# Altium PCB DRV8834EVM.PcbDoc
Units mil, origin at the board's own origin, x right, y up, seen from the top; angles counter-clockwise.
Board outline 5000 x 4500 mil, 2 copper layers (Top Layer, Bottom Layer); 84 components, 82 nets, 320 pads, 109 vias.
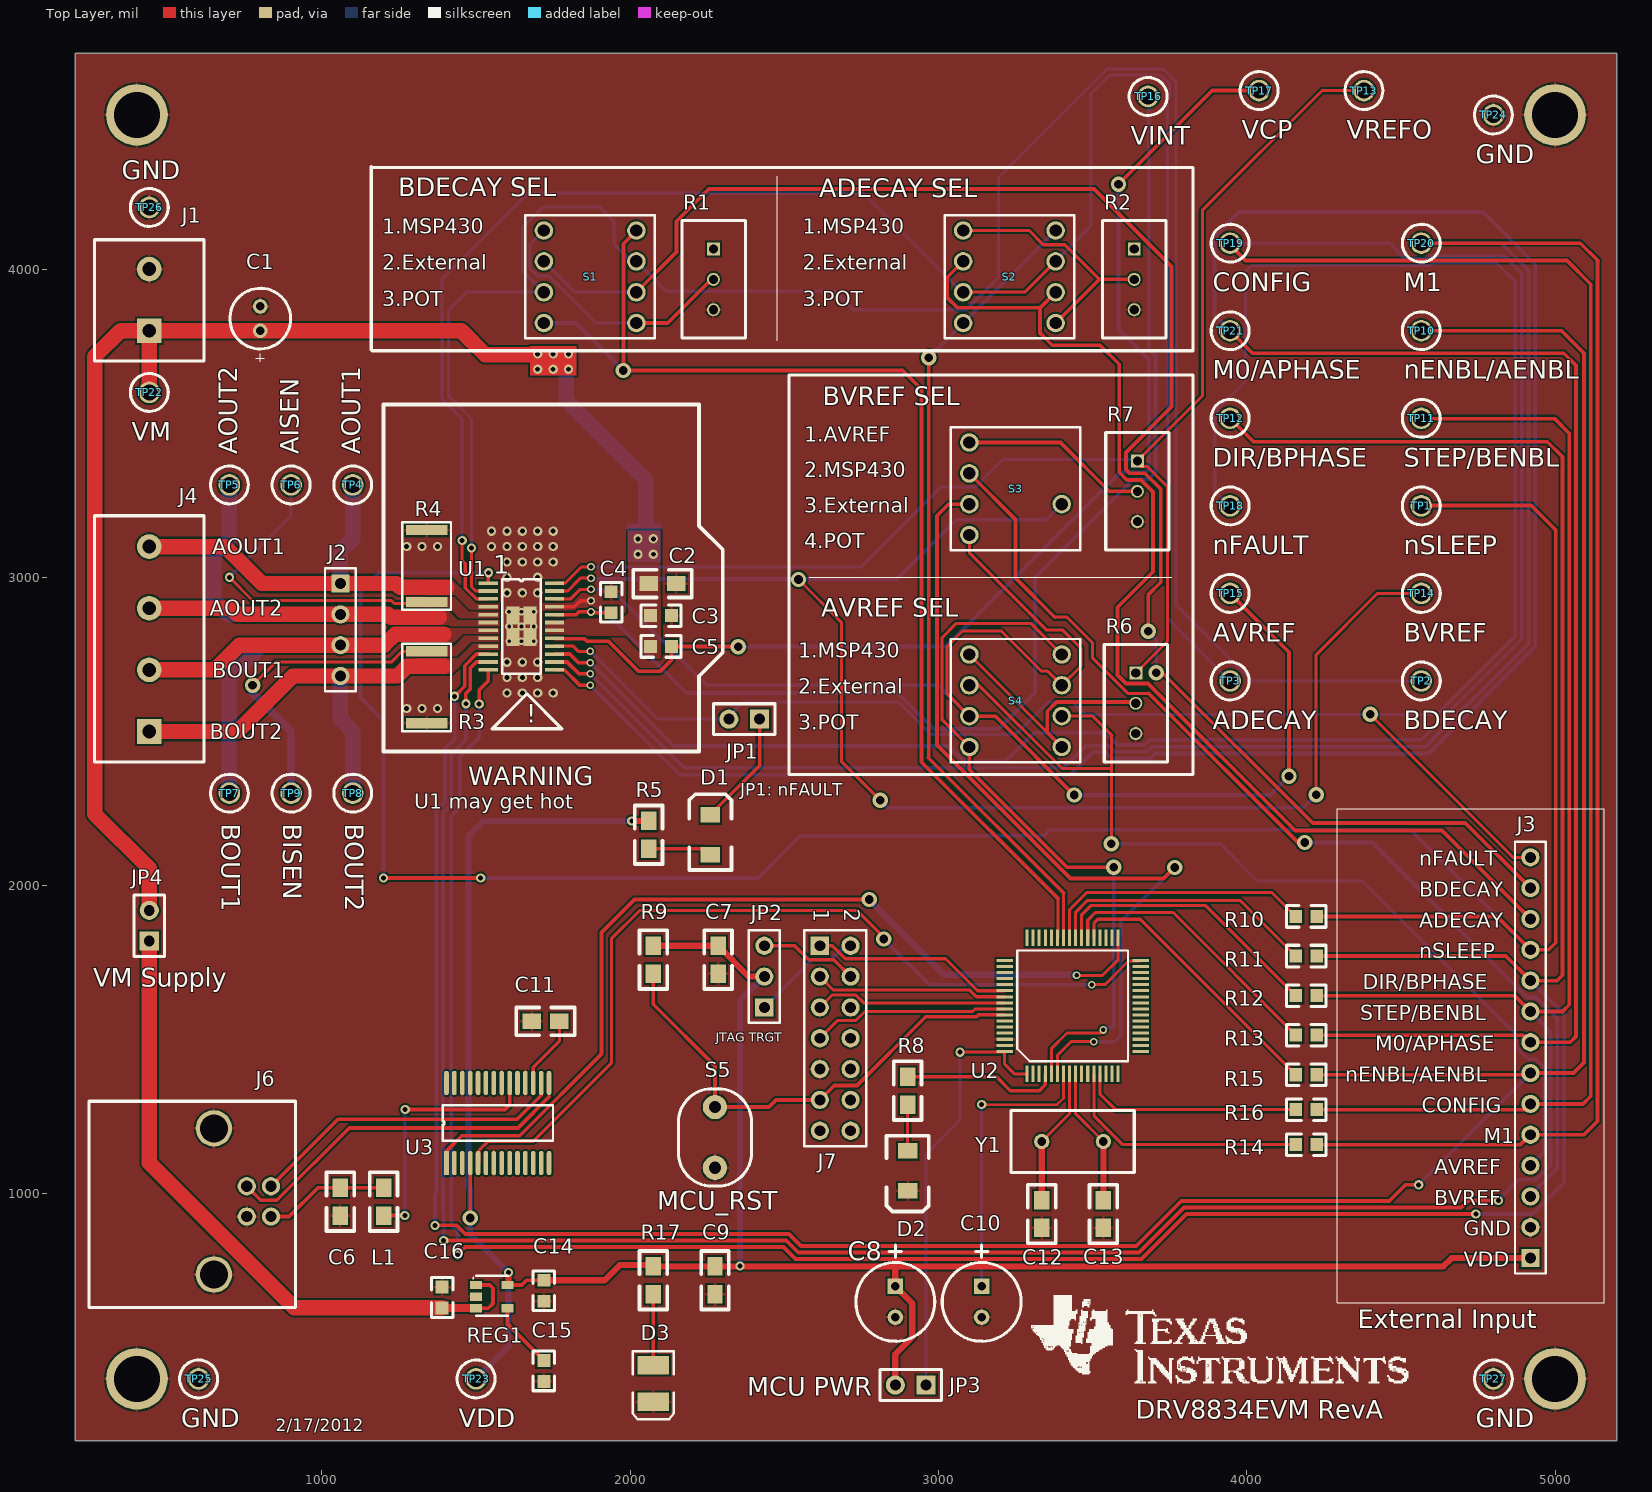
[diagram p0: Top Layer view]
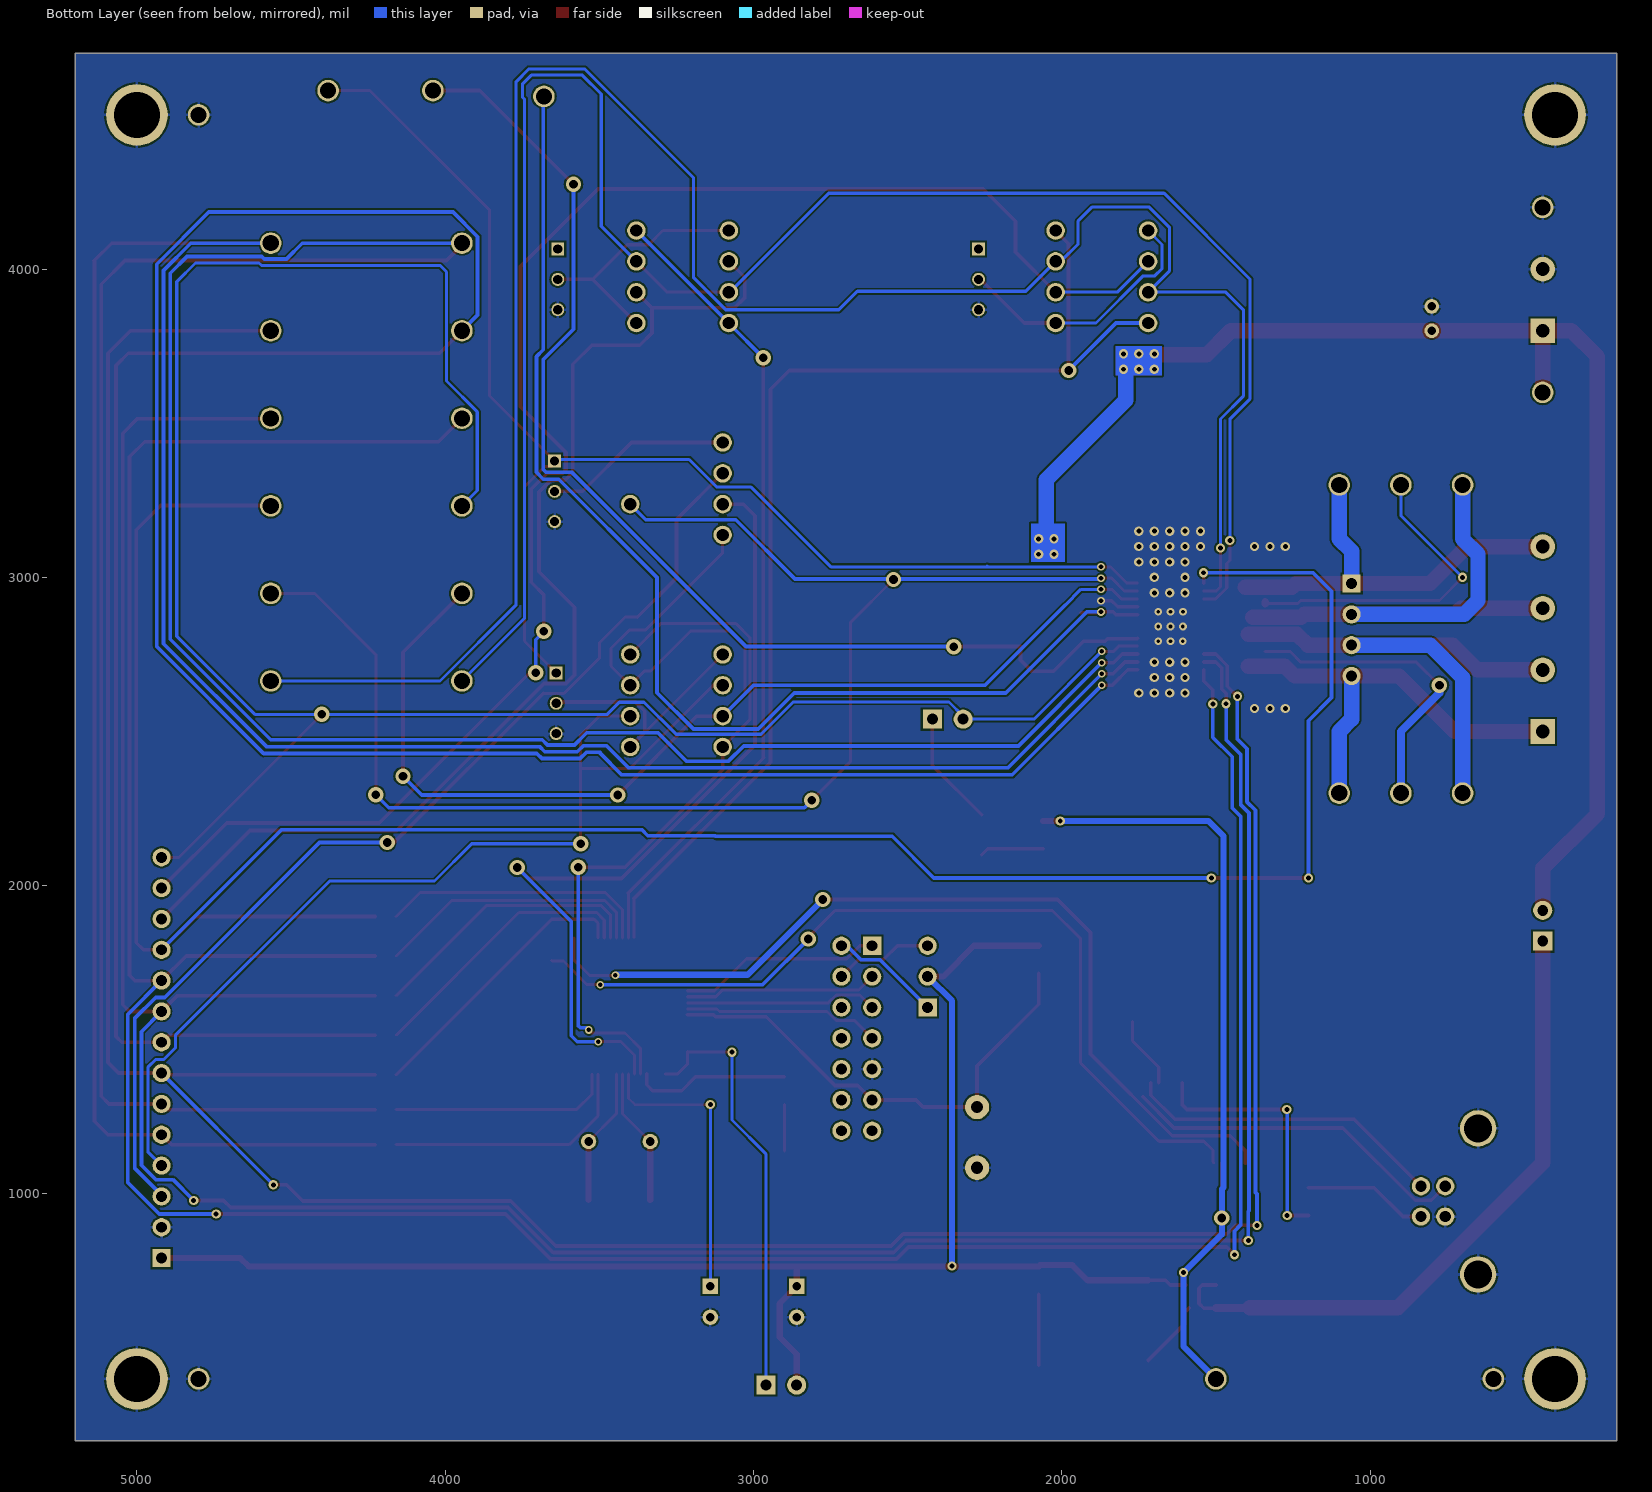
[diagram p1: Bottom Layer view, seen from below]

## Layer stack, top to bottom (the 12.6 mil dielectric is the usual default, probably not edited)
Top Layer: signal copper 1.4
Dielectric: dielectric 12.6, FR-4, Dk 4.8
Bottom Layer: signal copper 1.4

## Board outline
200,200 5200,200 5200,4700 200,4700 200,200

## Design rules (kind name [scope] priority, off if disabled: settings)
Clearance [All] p1: gap=6
HoleSize [All] p1: absolutevalues=TRUE maxlimit=150 minlimit=1 maxpercent=80.000 minpercent=20.000
HoleToHoleClearance [All] p1: gap=5 allowstackedmicrovias=TRUE
MinimumSolderMaskSliver [All] p1: minsoldermaskwidth=2
PasteMaskExpansion [All] p1: expansion=5
PolygonConnect PolygonConnect_2 [All vs IsNamedPolygon('TOP_BOUT2') Or  IsNamedPolygon('TOP_BOUT1') Or  IsNamedPolygon('TOP_BISEN') Or  IsNamedPolygon('TOP_AOUT2') Or  IsNamedPolygon('TOP_AISEN') Or  IsNamedPolygon('TOP_VM') Or  IsNamedPolygon('TOP_AOUT1')] p1: connectstyle=Direct reliefconductorwidth=10 reliefentries=4 polygonreliefangle="90 Angle"
PolygonConnect PolygonConnect_1 [All vs (InComponent('U1') or IsVia) AND InNet('GND')] p2: connectstyle=Direct reliefconductorwidth=10 reliefentries=4 polygonreliefangle="90 Angle"
PolygonConnect [All] p3: connectstyle=Relief reliefconductorwidth=10 reliefentries=4 polygonreliefangle="90 Angle"
RoutingVias [All] p1: holewidth=28 width=50 viastyle="Through Hole" minholewidth=10 minwidth=15 maxholewidth=150 maxwidth=150
SilkToSilkClearance [All] p1: silktosilkclearance=5
SilkscreenOverComponentPads [All] p1: minsilkscreentomaskgap=3
SolderMaskExpansion [All] p1: expansion=3
TestPointUsage [All] p1: valid=0 allowmultiple=FALSE
Testpoint [All] p1: side=15 testpointundercomponent=TRUE minsize=40 maxsize=100 preferedsize=60 minholesize=0 maxholesize=40 preferedholesize=32 testpointgrid=1 style=1023 order=0-112345678
Width [All] p1: maxlimit=100 minlimit=8 preferedwidth=10
18 further rules are at their usual default settings.

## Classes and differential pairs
component class DRV8834EVM_MSP430: C6 C7 C8 C9 C10 C11 C12 C13 C14 C15 C16 D2 D3 J6 J7 JP2 JP3 JP4 L1 R8 R9 R10 R11 R12 R13 R14 R15 R16 R17 REG1 S5 U2 U3 Y1
component class DRV8834EVM: AVREF BVREF C1 C2 C3 C4 C5 D1 GND J1 J2 J3 J4 JP1 R1 R2 R3 R4 R5 R6 R7 S1 S2 S3 S4 TP1 TP2 TP3 TP4 TP5 TP6 TP7 TP8 TP9 TP10 TP11 TP12 TP13 TP14 TP15 TP16 TP17 TP18 TP19 TP20 TP21 TP22 TP23 TP24 TP25 TP26 TP27 U1

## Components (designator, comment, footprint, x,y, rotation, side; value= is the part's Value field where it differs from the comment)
C1 "" "RB 2.0mm/5mm_NoPost" 800,3878.74 r270 top
C2 "" 0805 2150,2980 r180 top
C3 "" 0603 2134,2876 r180 top
C4 "" 0603 1938,2953.11 r270 top
C5 "" 0603 2065.89,2776 r0 top
C6 "" 0805 1060,930 r90 top
C7 "" 0805 2285,1715 r90 top
C8 "Cap Pol1" "RB .1/.250" 2860,600 r270 top
C9 "" 0805 2275,675 r90 top
C10 "Cap Pol1" "RB .1/.250" 3140,600 r270 top
C11 "" 0805 1680,1560 r0 top
C12 "Cap" 0805 3335,890 r90 top
C13 "Cap" 0805 3535,890 r90 top
C14 "2.2uF" 0603 1720,720 r270 top
C15 ".01uF" 0603 1720,460 r270 top
C16 "" 0603 1390,697.81 r270 top
D1 "nFAULT" 1206_LED 2260,2100 r90 top
D2 "Status" 1206_LED 2900,1140 r270 top
D3 "3.3V" 3.5X2.8X1.9 2075,385 r270 top
J1 "PWR" PWR_CONN2 440,3800 r90 top
J2 "Header 4" HDR1X4 1060,2980 r270 top
J3 "Input" HDR1X14 4920,792 r90 top
J4 "OUT" PWR_CONN4 440,2500 r90 top
J6 "USB B Conn" USB_CONN 756.26,1025 r270 top
J7 "JTAG" MSP430_JTAG 2615,1805 r270 top
JP1 "nFAULT" JMP0.2 2420,2540 r180 top
JP2 "PWR Select" HDR1X3 2435,1605 r90 top
JP3 "MCU PWR" JMP0.2 2960,380 r180 top
JP4 "VM" JMP0.2 440,1820 r90 top
L1 "" 0805 1200,1020 r270 top
R1 "" "PV36 Pot" 2270,4065.04 r0 top
R2 "" "PV36 Pot" 3635,4065.04 r0 top
R3 "" 2512 1340,2526.54 r90 top locked
R4 "" 2512 1340,3153.46 r270 top locked
R5 "" 0805 2060,2210 r270 top
R6 "" "PV36 Pot" 3640,2690.04 r0 top
R7 "" "PV36 Pot" 3645,3377.54 r0 top
R8 "Res2" 0805 2900,1290 r90 top
R9 "Res2" 0805 2075,1715 r90 top
R10 "Res1" 0603 4159.09,1900 r0 top
R11 "Res1" 0603 4159.09,1771.67 r0 top
R12 "Res1" 0603 4159.09,1643.33 r0 top
R13 "Res1" 0603 4159.09,1515 r0 top
R14 "Res1" 0603 4227,1160 r180 top
R15 "Res1" 0603 4159.09,1386.67 r0 top
R16 "Res1" 0603 4227,1273.33 r180 top
R17 "" 0805 2075,675 r90 top
REG1 "Volt_Reg LP2985" LP2985 1500,704.51 r270 top
S1 "BDECAY SEL" "SS10 3 Pos Selector - duplicate" 1720,4125 r0 top
S2 "ADECAY SEL" "SS10 3 Pos Selector - duplicate" 3080,4125 r0 top
S3 "BVREF SEL" "SS10 4 POS SELECTOR" 3100,3437.5 r0 top
S4 "AVREF SEL" "SS10 3 Pos Selector - duplicate" 3100,2750 r0 top
S5 "MCU-RST" Pana_PB 2275,1085 r90 top
TP1 "nSLEEP" "TEST POINT 0.052" 4566,3232 r0 top
TP2 "BDECAY" "TEST POINT 0.052" 4566,2664 r0 top
TP3 "ADECAY" "TEST POINT 0.052" 3946,2664 r0 top
TP4 "AOUT1" "TEST POINT 0.052" 1100,3300 r0 top
TP5 "AOUT2" "TEST POINT 0.052" 700,3300 r90 top
TP6 "AISEN" "TEST POINT 0.052" 900,3300 r0 top
TP7 "BOUT1" "TEST POINT 0.052" 700,2300 r270 top
TP8 "BOUT2" "TEST POINT 0.052" 1100,2300 r0 top
TP9 "BISEN" "TEST POINT 0.052" 900,2300 r0 top
TP10 "nENBL/AENBL" "TEST POINT 0.052" 4566,3800 r0 top
TP11 "STEP/BENBL" "TEST POINT 0.052" 4566,3516 r0 top
TP12 "DIR/BPHASE" "TEST POINT 0.052" 3946,3516 r0 top
TP13 "VREFO" "TEST POINT 0.052" 4380,4579 r0 top
TP14 "BVREF" "TEST POINT 0.052" 4566,2948 r0 top
TP15 "AVREF" "TEST POINT 0.052" 3946,2948 r0 top
TP16 "VINT" "TEST POINT 0.052" 3680,4560 r90 top
TP17 "VCP" "TEST POINT 0.052" 4040,4579 r90 top
TP18 "nFAULT" "TEST POINT 0.052" 3946,3232 r90 top
TP19 "CONFIG" "TEST POINT 0.052" 3946,4084 r90 top
TP20 "M1" "TEST POINT 0.052" 4566,4084 r90 top
TP21 "M0/APHASE" "TEST POINT 0.052" 3946,3800 r90 top
TP22 "VM" "TEST POINT 0.052" 440,3600 r0 top
TP23 "VDD" "TEST POINT 0.052" 1500,400 r0 top
TP24 "GND" "TEST POINT 0.052" 4800,4500 r90 top
TP25 "GND" "TEST POINT 0.052" 600,400 r90 top
TP26 "GND" "TEST POINT 0.052" 440,4200 r90 top
TP27 "GND" "TEST POINT 0.052" 4800,400 r90 top
U1 "DRV8834PWP" "DRV8834 (HTSSOP24)" 1540,2981.5 r0 top locked
U2 "MSP430F2617" MSP430F1612 3435,1610 r90 top locked
U3 "FTD232R" FT232RL 1404.09,1100.16 r90 top
Y1 "16 MHZ" XTAL 3535,1170 r180 top

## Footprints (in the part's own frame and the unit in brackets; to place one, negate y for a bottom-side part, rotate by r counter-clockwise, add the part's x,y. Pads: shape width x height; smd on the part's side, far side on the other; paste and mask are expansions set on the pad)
3.5X2.8X1.9 [mm] "SM LED; 2 C-Bend Leads; Body 3.5 x 2.8 x 1.9 mm, inc leads (LxWxH typ)"
  rect 1.5x2.6 smd: 1(-1.5,0) 2(1.5,0)
  silkscreen extent -2.65,-1.7 2.95,1.7
0603 [mm]
  rect 1.05x1.08 smd: 1(0,0) 2(1.73,0)
  silkscreen extent -0.77,-0.89 2.5,0.89
0805 [mil]
  rect 60x50 smd: 1(0,0) 2(90,0)
  silkscreen extent -50,-45 140,45
1206_LED [mm]
  rect 1.3x1.6 smd: 1(0,0) 2(3.3,0)
  silkscreen extent -1.25,-1.75 5,1.75
2512 [mm]
  rect 0.85x3.4 smd: 1(0,0) 2(5.93,0)
  silkscreen extent -0.64,-2 6.57,2
"DRV8834 (HTSSOP24)" [mm]
  rect 1.1x1.5 smd: 0(2.032,-4.445) 0(2.032,-2.667) 0(3.429,-4.445) 0(3.429,-2.667)
  rect 1.6x0.3 smd mask+0.07: 1(0,0) 2(0,-0.65) 3(0,-1.3) 4(0,-1.95) 5(0,-2.6) 6(0,-3.25) 7(0,-3.9) 8(0,-4.55) 9(0,-5.2) 10(0,-5.85) 11(0,-6.5) 12(0,-7.15) 13(5.45,-7.15) 14(5.45,-6.5) 15(5.45,-5.85) 16(5.45,-5.2) 17(5.45,-4.55) 18(5.45,-3.9) 19(5.45,-3.25) 20(5.45,-2.6) 21(5.45,-1.95) 22(5.45,-1.3) 23(5.45,-0.65) 24(5.45,0)
  silkscreen extent 1.14,-7.48 4.32,0.33
FT232RL [mm]
  rect 2x0.381 smd: 1(0,0)
  oval 2x0.381 smd: 2(0,-0.65) 3(0,-1.3) 4(0,-1.95) 5(0,-2.6) 6(0,-3.25) 7(0,-3.9) 8(0,-4.55) 9(0,-5.2) 10(0,-5.85) 11(0,-6.5) 12(0,-7.15) 13(0,-7.8) 14(0,-8.45) 15(6.6,-8.45) 16(6.6,-7.8) 17(6.6,-7.15) 18(6.6,-6.5) 19(6.6,-5.85) 20(6.6,-5.2) 21(6.6,-4.55) 22(6.6,-3.9) 23(6.6,-3.25) 24(6.6,-2.6) 25(6.6,-1.95) 26(6.6,-1.3) 27(6.6,-0.65) 28(6.6,0)
  silkscreen extent 1.84,-8.78 4.76,0.33
HDR1X3 [mm] "Connector; Header; 3 Position"
  rect 1.5x1.5 hole 0.9: 1(0,0)
  round 1.5 hole 0.9: 2(2.54,0) 3(5.08,0)
  silkscreen extent -1.27,-1.27 6.35,1.27
HDR1X4 [mm] "Connector; Header; 4 Position"
  rect 1.5x1.5 hole 0.9: 1(0,0)
  round 1.5 hole 0.9: 2(2.54,0) 3(5.08,0) 4(7.62,0)
  silkscreen extent -1.27,-1.27 8.89,1.27
HDR1X14 [mm] "Connector; Header; 14 Position"
  rect 1.5x1.5 hole 0.9: 1(0,0)
  round 1.5 hole 0.9: 2(2.54,0) 3(5.08,0) 4(7.62,0) 5(10.16,0) 6(12.7,0) 7(15.24,0) 8(17.78,0) 9(20.32,0) 10(22.86,0) 11(25.4,0) 12(27.94,0) 13(30.48,0) 14(33.02,0)
  silkscreen extent -1.27,-1.27 34.29,1.27
JMP0.2 [mil]
  rect 62x62 hole 35.43: 1(0,0)
  round 62 hole 35.43: 2(100,0)
  silkscreen extent -50,-50 150,50
LP2985 [mil] "SOT-23/SC-74A; 5 Leads; Body 3.1 x 3 mm, inc. leads (LxW max)"
  rect 27x39 smd: 1(0,0) 2(37.5,0) 3(75,0) 4(75,102) 5(0,102)
  silkscreen extent -30,-11 100,102
MSP430_JTAG [mm] "Connector; Header; 7x2 Position"
  rect 1.5x1.5 hole 0.9: 1(0,0)
  round 1.5 hole 0.9: 2(0,2.54) 3(2.54,0) 4(2.54,2.54) 5(5.08,0) 6(5.08,2.54) 7(7.62,0) 8(7.62,2.54) 9(10.16,0) 10(10.16,2.54) 11(12.7,0) 12(12.7,2.54) 13(15.24,0) 14(15.24,2.54)
  silkscreen extent -1.27,-1.27 16.51,3.81
MSP430F1612 [mm]
  rect 1.35x0.25 smd: 1(-5.6,3.75) 2(-5.6,3.25) 3(-5.6,2.75) 4(-5.6,2.25) 5(-5.6,1.75) 6(-5.6,1.25) 7(-5.6,0.75) 8(-5.6,0.25) 9(-5.6,-0.25) 10(-5.6,-0.75) 11(-5.6,-1.25) 12(-5.6,-1.75) 13(-5.6,-2.25) 14(-5.6,-2.75) 15(-5.6,-3.25) 16(-5.6,-3.75) 33(5.6,-3.75) 34(5.6,-3.25) 35(5.6,-2.75) 36(5.6,-2.25) 37(5.6,-1.75) 38(5.6,-1.25) 39(5.6,-0.75) 40(5.6,-0.25) 41(5.6,0.25) 42(5.6,0.75) 43(5.6,1.25) 44(5.6,1.75) 45(5.6,2.25) 46(5.6,2.75) 47(5.6,3.25) 48(5.6,3.75)
  rect 0.25x1.35 smd: 17(-3.75,-5.6) 18(-3.25,-5.6) 19(-2.75,-5.6) 20(-2.25,-5.6) 21(-1.75,-5.6) 22(-1.25,-5.6) 23(-0.75,-5.6) 24(-0.25,-5.6) 25(0.25,-5.6) 26(0.75,-5.6) 27(1.25,-5.6) 28(1.75,-5.6) 29(2.25,-5.6) 30(2.75,-5.6) 31(3.25,-5.6) 32(3.75,-5.6) 49(3.75,5.6) 50(3.25,5.6) 51(2.75,5.6) 52(2.25,5.6) 53(1.75,5.6) 54(1.25,5.6) 55(0.75,5.6) 56(0.25,5.6) 57(-0.25,5.6) 58(-0.75,5.6) 59(-1.25,5.6) 60(-1.75,5.6) 61(-2.25,5.6) 62(-2.75,5.6) 63(-3.25,5.6) 64(-3.75,5.6)
  silkscreen extent -4.56,-4.56 4.56,4.56
Pana_PB [mm] "Panasonic EVQ-11A04M Push Button"
  round 2 hole 1: 1(0,0) 2(5,0)
  silkscreen extent -1.51,-3 6.51,3
"PV36 Pot" [mil] "25 Turn Cermet Trimmer"
  rect 42x42 hole 29.53: 1(0,0)
  round 42 hole 29.53: 2(0,-98.43) 3(0,-196.85)
  silkscreen extent -102,-289 103,93
PWR_CONN2 [mil]
  rect 80x80 hole 45: 1(0,0)
  round 80 hole 45: 2(200,0)
  silkscreen extent -98,-177 295,177
PWR_CONN4 [mil]
  rect 80x80 hole 45: 1(0,0)
  round 80 hole 45: 2(200,0) 3(400,0) 4(600,0)
  silkscreen extent -98,-177 700,177
"RB 2.0mm/5mm_NoPost" [mm] "2mmLead spacing and 5 mm Dia"
  round 1.2 hole 0.7: 1(2,0) 2(0,0)
  silkscreen extent -1.5,-2.5 4.55,2.5
"RB .1/.250" [mil]
  rect 50x50 hole 28: 1(-100,0)
  round 50 hole 28: 2(0,0)
  silkscreen extent -234,-128 78,128
"SS10 3 Pos Selector - duplicate" [mil]
  round 60 hole 40: 1(0,-300) 1(300,0) 2(0,-100) 2(300,-200) 3(0,0) 3(300,-300) C(0,-200) C(300,-100)
  silkscreen extent -60,-350 360,50
"SS10 4 POS SELECTOR" [mil]
  round 60 hole 40: 1(0,-300) 2(0,-200) 3(0,-100) 4(0,0) C(300,-200)
  silkscreen extent -60,-350 360,50
"TEST POINT 0.052" [mil] "Glass Beaded Test Point"
  round 70 hole 52: 1(0,0)
  silkscreen extent -61,-61 62,61
USB_CONN [mm] "USB Right Angle receptacle"
  round 1.5 hole 0.93: 1(2.5,2) 2(0,2) 3(0,0) 4(2.5,0)
  round 3 hole 2.3: 5(-4.77,-2.71) 6(7.27,-2.71)
  silkscreen extent -7,-13 10,4
XTAL [mil]
  round 50 hole 28: 1(0,0) 2(200,0)
  silkscreen extent -100,-100 300,100

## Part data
C1: library part "Cap Pol1", "Polarized Capacitor (Radial)"
C2 C3 C5 C14 C15 C16: library part Cap, "Capacitor"
C4: library part Cap1, "CAP CER 2.2UF 10V Y5V 0603"
C6 C7 C9 C11: library part Cap, "CAP .10UF 50V CERAMIC X7R 0805"
C8 C10: "10uF, 25V Electrolytic Cap (Radial)"
C12 C13: "CAP CERAMIC 33PF 50V NP0 0805"
D1: library part LED3, "LED RED CLEAR 1206 SMD"
D2 D3: library part LED3, "LED RED Clear 1206 SMD"
J1: library part "Header 2", "TERM BLOCK 5.08MM VERT 2POS PCB"
J2: library part "Header 2"
J3: library part "Header 14", "CONN HEADER .100 SINGL STR 14POS"
J4: library part "Header 4", "TERM BLOCK 5.08MM VERT 4POS PCB"
J6: library part USB_B_CONN, "CONN USB RT ANG RECPT TYPE B BLK"
J7: library part "Header 7X2H", "CONN HEADER .100 DUAL STR 14POS"
JP1 JP3 JP4: library part "JUMPER 2 PIN", "Two Pin Jumper"
JP2: library part "Header 3", "CONN HEADER .100 SINGL STR 3POS"
L1: library part Inductor, "Ferrite Bead 1.5A 40 ohm 0805 SMD"
R1 R2 R6 R7: library part PV37Y103C01B00, "TRIMMER 10K OHM 0.25W TH"
R3 R4: library part "Sense Res", "RES .4OHM 2W 1% 2512 SMD"
R5: library part Res1, "Resistor"
R8: "RES 330 OHM 1/8W 5% 0805 SMD"
R9: "RES 3.3K OHM 1/8W 5% 0805 SMD"
R10 R11 R12 R13 R14 R15 R16: "Resistor"
R17: library part Res1, "RES 330 OHM 1/8W 5% 0805 SMD"
REG1: "VoltageRegulator"
S1 S2 S4: library part "SS10 3 Pos Selector"
S3: library part "SS10 4 Pos Selector"
S5: library part SW-PB, "SWITCH LIGHT TOUCH 4.3MM 100GF"
TP1 TP2 TP3 TP4 TP5 TP6 TP7 TP8 TP9 TP10 TP11 TP12 TP13 TP14 TP15 TP16 TP17 TP18 TP19 TP20 TP21 TP22 TP23 TP24 TP25 TP26 TP27: library part "TEST POINT", "Glass Beaded Test Point"
U1: "Stepping and DC motor Driver"
U2: library part MSP430F1612, "IC MCU 16BIT 55K FLASH 64-LQFP"
U3: library part FT232R, "USB Chip"
Y1: library part XTAL, "CRYSTAL 8.00 MHZ 20PF 49US"

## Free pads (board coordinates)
  round 200 hole 150: 0(400,400) 0(400,4500) 0(5000,400) 0(5000,4500)

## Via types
v1: diameter 30, hole 16, Top Layer to Bottom Layer, 67 vias
v2: diameter 50, hole 28, Top Layer to Bottom Layer, 20 vias
v3: diameter 25, hole 15, Top Layer to Bottom Layer, 13 vias
v4: diameter 25, hole 12, Top Layer to Bottom Layer, tented both sides, 9 vias

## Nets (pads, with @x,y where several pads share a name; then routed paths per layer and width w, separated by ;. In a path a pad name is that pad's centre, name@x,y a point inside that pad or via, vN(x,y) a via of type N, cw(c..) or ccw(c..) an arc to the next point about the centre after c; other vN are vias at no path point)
5VCC: L1.2 U3.20 | length 829.1
  Top Layer w12: L1.2 v1(1269,930) ; v1(1270,1274) 1594,1274 1608.82,1288.82 U3.20
  Bottom Layer w12: v1(1269,930) v1@1269,1274
ADECAY: S2.C TP3.1 U1.3 | length 6308.7
  Top Layer w10: v1(1455,3120) 1455,3055 1465,3045 1465,2965.63 1500.32,2930.32 U1.3 ; S2.C@3080,3925 3280,3925 S2.C@3380,4025
  Bottom Layer w10: v1(1455,3120) 1455,3513 1390,3578 1390,3968 1668,4246 2756,4246 3077,3925 S2.C@3080,3925 ; S2.C@3380,4025 3494,4139 3494,4567.72 3555.28,4629 3720.71,4629 3750,4599.71 3750,4558.29 3743,4551.29 3743,2867 TP3.1
AISEN: R4.2 TP6.1 U1.5 | length 1063
  Top Layer w10: v1(700,3000) 775,2925 1225,2925 1234.99,2915.01 R4.2@1340,2915.01
  Top Layer w25: R4.2@1340,2915.01 R4.2
  Bottom Layer w10: v1(700,3000) 900,3200 TP6.1
AOUT1: J2.1 J4.4 TP4.1 U1.4 | length 1356.4
  Top Layer w50: J4.4 685,3100 805,2980 J2.1 1241,2980 1253.27,2967.73 1405,2967.73
  Bottom Layer w50: J2.1 1060,3085 1100,3125 TP4.1
AOUT2: J2.2 J4.3 TP5.1 U1.6 | length 1776.4
  Top Layer w50: J4.3 705,2900 725,2880 J2.2 1214,2880 1223,2871 1380,2871
  Bottom Layer w50: TP5.1 700,3125 650,3075 650,2925 695,2880 J2.2
AVREF: S3.1 S4.C TP15.1 U1.22 | length 4783.8
  Top Layer w10: U1.22 1807.32,2930.32 1838,2961 v3(1873,2961) ; S4.C@3100,2550 3028,2622 3028,2776 3078,2826 3204,2826 3334,2696 3354,2696 3400,2650 3462,2712 3462,2770 3403,2829 3351,2829 3100,3080 S3.1
  Top Layer w12: S4.C@3100,2550 3184,2550 v2(3440,2294) ; TP15.1 4137,2757 v2(4137,2355)
  Bottom Layer w10: v3(1873,2961) 1938.11,2961 1989.11,2910
  Bottom Layer w12: 1989.11,2910 2249.11,2650 3000,2650 S4.C@3100,2550 ; v2(3440,2294) 4076,2294 v2(4137,2355)
BDECAY: S1.C TP2.1 U1.2 | length 7016.1
  Top Layer w10: v1(1485,3095) 1485,2970 1499.09,2955.91 U1.2
  Bottom Layer w10: v1(1485,3095) 1485,3514 1411,3588 1411,3868 1468,3925 1720,3925 1650,3995 1650,4134 1718,4202 1901,4202 1948,4155 1948,4080 2003,4025 2020,4025 2117,3928 2663,3928 2723,3868 3090,3868 3195,3973 3195,4297 3547,4649 3728.99,4649 3770,4607.99 3770,2911 4017,2664 TP2.1
BISEN: R3.2 TP9.1 U1.8 | length 1012.3
  Top Layer w10: v2(775,2650) 850,2725 1225,2725 1260,2760 R3.2
  Bottom Layer w25: v2(775,2650) 775,2625 900,2500 TP9.1
BOUT1: J2.3 J4.2 TP7.1 U1.7 | length 1781.1
  Top Layer w50: J4.2 652,2700 732,2780 J2.3 1202,2780 1237,2815 1395,2815
  Bottom Layer w50: TP7.1 700,2675 805,2780 J2.3
BOUT2: J2.4 J4.1 TP8.1 U1.9 | length 1439.4
  Top Layer w50: J4.1 726,2500 906,2680 J2.4 1245,2680 1277,2712 1395,2712
  Bottom Layer w50: J2.4 1060,2540 1100,2500 TP8.1
BVREF: S3.C TP14.1 U1.23 | length 4908.7
  Top Layer w10: U1.23 1796.91,2955.91 1838.5,2997.5 v3(1873,2997.5) ; v2(2546,2993) 2686,2853 2686,2402 v2(2811,2277) ; v2(4225,2295) 4225,2749 4424,2948 TP14.1
  Bottom Layer w12: v3(1873,2997.5) 1875.5,2995 2546,2995 2865.5,2995 3057.5,3187 3349.5,3187 S3.C ; v2(2811,2277) 2835,2253 4183,2253 v2(4225,2295)
CBUS0: U3.23
CBUS1: U3.22
CBUS2: U3.13
CBUS3: U3.14
CBUS4: U3.12
CONFIG: J3.6 R16.1 TP19.1 U1.15 | length 10420.8
  Top Layer w12: U1.15 1803.82,2751.18 1831.5,2723.5 v3(1870,2723.5) ; TP19.1 3946,4078 3996,4028 5039,4028 5116,3951 5116,1317 5091,1292 J3.6 4901.33,1273.33 R16.1
  Bottom Layer w12: v3@1870.27,2723.5 2140.77,2453 3031.95,2453 3080.95,2404 3218,2404 3310,2496 3541,2496 ; 3546,2491 3580.81,2456.19 3668.21,2456.19 3685.02,2473 4566,2473 4892,2799 4892,3986.7 4837.7,4041 4595.12,4041 4587.12,4033 4515,4033 4464,4084 TP19.1
CTS: U3.11
DCD: U3.10
DEVSEL: U2.49
DIR/BPHASE: J3.10 R11.2 TP12.1 U1.12 | length 10023.1
  Top Layer w12: v1(1439.78,802.78) 1465,828 2497.3,828 2536.3,789 3658.7,789 3804.7,935 v1(4743,935) ; v1(1510,2589) 1510,2635 1540,2665 U1.12 ; TP12.1 4022,3440 4975,3440 5024,3391 5024,1709 5007,1692 J3.10 4840.33,1771.67 R11.2
  Bottom Layer w12: v1(1439.78,802.78) 1439.78,879.22 1420,899 1420,2224.82 1447,2251.82 1447,2418 1510,2481 v1(1510,2589) ; v1(4743,935) 4927.39,935 5029.53,1037.14 5029.53,1582.47 J3.10
DSR: U3.9
DTR: U3.2
EXT_ADECAY: J3.12 S2.2 | length 3702.1
  Top Layer w12: S2.2@3080,4025 3030,3975 3028,3975 3028,3908 3061,3875 3328,3875 3329,3874 ; S2.2@3380,3925 3329,3874 ; J3.12 4633,2179 4157,2179 3680,2656 3608,2656 3581,2683 3581,2903 3696,3018 3696,3277 3656.89,3316.11 3610.69,3316.11 3586,3340.8 3586,3691 3524,3753 3369,3753 3329,3793 3329,3874
EXT_AVREF: J3.4 S4.2 | length 3192.1
  Top Layer w10: S4.2@3100,2650 3131,2650 3401,2380 3558,2380 3561,2383 ; S4.2@3400,2550 3500,2550 3561.93,2488.07 3561,2487.14 3561,2383 ; v2(3561,2136) 3561,2383
  Bottom Layer w10: v2@3548,2136 v2(3561,2136) 3914,2136 4035,2015 4375,2015 4875.47,1514.53 4875.47,1473.56 4912.5,1436.53 4938.44,1436.53 4964.53,1410.44 4964.53,1136.53 J3.4
EXT_BDECAY: J3.13 S1.2 | length 5365
  Top Layer w12: S1.2@2020,3925 2150,4055 2150,4155 2255,4260 3504.67,4260 3756,4008.67 3756,3553.17 3608,3405.17 3608,3349.91 3619.8,3338.11 3669.44,3338.11 3721,3286.55 3721,2984 3680,2943 v2(3680,2825) ; v2(3706,2691) 3726.1,2691 4214.1,2203 4709,2203 J3.13
  Bottom Layer w10: S1.2@1720,4025 1820,3925 S1.2@2020,3925
  Bottom Layer w12: v2(3680,2825) 3680,2824 3706,2798 v2(3706,2691)
EXT_BVREF: J3.3 S3.3 | length 3393.5
  Top Layer w10: 3377,2871 3417,2871 3499,2789 3499,2739 3614.39,2623.61 3682.39,2623.61
  Top Layer w12: S3.3 3250,3187.5 3250,2998 3377,2871 ; 3682.39,2623.61 4166,2140 v2(4188,2140)
  Bottom Layer w12: v2(4188,2140) 4407.61,2140 4910.09,1637.53 4938.86,1637.53 5007.53,1568.86 5007.53,1084.03 4920,996.5 J3.3
GND: C1.2 C2.1 C3.1 C4.1 C6.1 C7.1 C8.2 C9.1 C10.2 C11.1 C12.1 C13.1 C14.2 C15.2 C16.1 D2.2 D3.2 J1.2 J3.2 J6.4 J6.5 J6.6 J7.9 pad.0 R1.3 R2.3 R3.1 R4.1 R6.3 R7.3 REG1.2 S5.1 TP24.1 TP25.1 TP26.1 TP27.1 U1.0 U1.21 U2.62 U2.63 U3.7 U3.18 U3.21 U3.25 U3.26 | length 126.6
  Top Layer w12: U1.21 1818.72,2904.72 1838.5,2924.5 v3(1873,2924.5)
  other v1: 1275,2575 1325,2575 1375,2575 1600,2625 1650,2625 1700,2625 1750,2625 1600,2675 1650,2675 1700,2675 1600,2725 1650,2725 1700,2725 1600,2950 1650,2950 1700,2950 1600,3000 1700,3000 1600,3050 1650,3050 1700,3050 1750,3050 1275,3100 1325,3100 1375,3100 1550,3100 1600,3100 1650,3100 1700,3100 1750,3100 1550,3150 1600,3150 1650,3150 1700,3150 1750,3150
  other v4: 1608,2793.25 1647.28,2793.25 1687.39,2793.25 1607.18,2840.75 1647.28,2840.75 1687.39,2840.75 1607,2888.25 1647.28,2888.25 1687.39,2888.25
M0/APHASE: J3.8 R13.2 TP21.1 U1.13 | length 10424.4
  Top Layer w12: U1.13 1786,2700 1835.5,2650.5 v3(1870,2650.5) ; TP21.1 4019,3727 5028,3727 5068,3687 5068,1511 5049,1492 J3.8 4897,1515 R13.2
  Bottom Layer w12: v3(1870,2650.5) 2160.5,2360 3428,2360 3500,2432 ; 3497.23,2433 3540,2433 ; 3542.77,2432 3562.59,2412.19 3686.44,2412.19 3703.25,2429 4589.11,2429 4936,2775.89 4936,4016 4767,4185 3974.88,4185 3895,4105.12 3895,3851 TP21.1
M1: J3.5 R14.1 TP20.1 U1.14 | length 9409.3
  Top Layer w12: U1.14 1795.41,2725.59 1834,2687 v3(1870,2687) ; R14.1 4888,1160 J3.5 5094,1192 5138,1236 5138,4026 ; TP20.1 5082,4084 5139,4027
  Bottom Layer w12: v3@1870.27,2687 2175.27,2382 3404.89,2382 3476.89,2454 3551.89,2454 3571.7,2434.19 3677.33,2434.19 3694.14,2451 4580,2451 4914,2785 4914,3995.81 4825.81,4084 TP20.1
MSP_ADECAY: S2.1 U2.42 | length 2646.9
  Top Layer w10: U2.42@3406,1831 3406,1976
  Top Layer w12: v2(2968,3712) 2968,2416 2967,2415 3406,1976
  Bottom Layer w12: v2(2968,3712) 3080,3824 3080,3825 S2.1@3380,4125
MSP_AVREF: S4.1 U2.5 | length 2343.5
  Top Layer w10: S4.1@3100,2450 3012,2538 3012,2805 3058,2851 3299,2851 S4.1@3400,2750 ; U2.5 3366.1,1471.1 3417,1522 3525,1522 3534,1531 v3(3534,1532)
  Top Layer w12: S4.1@3100,2450 3100,2376.46 3416.46,2060 v2(3568,2060)
  Bottom Layer w12: v3(3534,1532) 3541,1539 3562,1539 3569,1546 3569,2059 v2(3568,2060)
MSP_BDECAY: S1.1 U2.43 | length 3746.6
  Top Layer w10: U2.43@3387.5,1832.18 3387.5,1958
  Top Layer w12: S1.1@2020,4125 2020,4124 1978,4082 v2(1978,3671) 2884,3671 2945,3610 2945,2400.5 3387.5,1958
  Bottom Layer w12: S1.1@1720,3825 1824,3825 v2(1978,3671)
MSP_BVREF: S3.2 U2.6 | length 2739.9
  Top Layer w10: U2.6 3385.79,1449.79 3430,1494 v3(3504,1494)
  Top Layer w12: S3.2 3032.5,3237.5 2995,3200 2995,2456 3428,2023 3730,2023 v2(3766,2059)
  Bottom Layer w12: v3(3504,1494) 3572,1494 3591,1513 3591,1884 v2(3766,2059)
NENBL/AENBL: J3.7 R15.2 TP10.1 U1.10 | length 9504.1
  Top Layer w12: v1(1367,898) 1437,898 1465,870 2514.7,870 2553.7,831 3641.3,831 3787.3,977 4462,977 4514.63,1029.63 v1(4557.63,1029.63) ; v1(1430,2614) 1463,2647 1463,2713.46 1500.73,2751.18 U1.10 ; R15.2 4914.67,1386.67 J3.7 5060,1392 5094,1426 5094,3727 5021,3800 TP10.1
  Bottom Layer w12: v1(1367,898) 1367,1000 1372,1005 1372,2244.7 1399,2271.7 1399,2444 1431,2476 1431,2613 v1(1430,2614) ; v1(4557.63,1029.63) J3.7
NetC6_2: C6.2 J6.1 L1.1 | length 403.7
  Top Layer w12: J6.1 893.57,926.57 987,1020 C6.2 L1.1
NetC10_1: C10.1 U2.7 | length 943
  Top Layer w8: v1(3140,1290) 3385,1290 3405.47,1310.47
  Top Layer w10: 3405.47,1310.47 U2.7
  Bottom Layer w10: C10.1 v1(3140,1290)
NetC11_2: C11.2 U3.17 | length 235
  Top Layer w10: U3.17 1685.59,1411.28 1770,1495.69 C11.2
NetC12_2: C12.2 U2.8 Y1.2 | length 446.9
  Top Layer w10: Y1.2 3425.16,1260.16 U2.8
  Top Layer w20: C12.2 Y1.2
NetC13_2: C13.2 U2.9 Y1.1 | length 446.9
  Top Layer w10: U2.9 3444.84,1260.16 Y1.1
  Top Layer w20: C13.2 Y1.1
NetC15_1: C15.1 REG1.4 | length 237
  Top Layer w12: REG1.4@1586.61,629.7 1594.41,621.91 REG1.4@1602,621.91 ; REG1.4 REG1.4@1602,621.91 ; C15.1 1602,578 REG1.4@1602,621.91
NetC16_2: C16.2 JP4.1 REG1.1 REG1.3 | length 2148.4
  Top Layer w12: REG1.3 1539.51,629.51 1555,645 1555,694.02 1544.51,704.51 REG1.1 ; REG1.3@1500,629.7 REG1.3@1504.91,629.7
  Top Layer w25: C16.2 REG1.3@1500,629.7
  Top Layer w50: JP4.1 440,1101 910,631 C16.2@1390,631
NetD1_1: D1.1 R5.2 | length 208.3
  Top Layer w12: R5.2 2240,2120 D1.1
NetD1_2: D1.2 JP1.1 | length 376.4
  Top Layer w12: D1.2 2420,2389.92 JP1.1
NetD2_1: D2.1 R8.1 | length 150
  Top Layer w10: D2.1 R8.1
NetD3_1: D3.1 R17.1 | length 230.9
  Top Layer w12: D3.1 R17.1
NetJ7_1: J7.1 U2.54 | length 659.9
  Top Layer w10: J7.1 2655.56,1805 2697.59,1762.97 3023.03,1762.97 3126.79,1659.21 U2.54
NetJ7_2: J7.2 JP2.1 | length 362.8
  Bottom Layer w12: JP2.1 2589.47,1759.47 2651.16,1759.47 2696.68,1805 J7.2
NetJ7_3: J7.3 U2.55 | length 626.6
  Top Layer w10: J7.3 2657.97,1662.03 3100.19,1662.03 3122.69,1639.53 U2.55
NetJ7_4: J7.4 JP2.3 | length 321.4
  Top Layer w12: JP2.3 2533.32,1805 2578.84,1759.47 2660.53,1759.47 J7.4
NetJ7_5: J7.5 U2.56 | length 627
  Top Layer w10: J7.5 2655.53,1645.53 2731.79,1645.53 2757.47,1619.84 U2.56
NetJ7_7: J7.7 U2.57 | length 638.9
  Top Layer w10: J7.7 2672.97,1562.97 2732.41,1562.97 2761.44,1592 3110.5,1592 3118.66,1600.16 U2.57
NetR1_2: R1.2 S1.3 | length 874
  Top Layer w10: R1.2@2266.61,3970 R1.2
  Top Layer w12: S1.3@2020,3825 2121.61,3825 2263.23,3966.61 R1.2
  Bottom Layer w10: S1.3@1720,4125 1675,4080 1675,4001 1698,3978 1736,3978 1889,3825 S1.3@2020,3825
NetR2_2: R2.2 S2.3 | length 820.6
  Top Layer w10: S2.3@3080,4125 3294,4125 3340,4079 3410,4079 3521.61,3967.39
  Top Layer w12: S2.3@3380,3825 3521.61,3966.61 R2.2
NetR6_2: R6.2 S4.3 | length 794.5
  Top Layer w10: S4.3@3100,2750 3353,2497
  Top Layer w12: S4.3@3400,2450 3353,2497 3353,2566 3383,2596 3635.61,2596 R6.2
NetR7_2: R7.2 S3.4 | length 610.6
  Top Layer w12: S3.4 3395.5,3437.5 3553.89,3279.11 R7.2
NetR10_1: R10.1 U2.41 | length 880.7
  Top Layer w10: U2.41 3425.16,1922.33 3480.33,1977.5 4081.59,1977.5 R10.1
NetR11_1: R11.1 U2.40 | length 888.4
  Top Layer w10: U2.40 3444.84,1914.26 3482.58,1952 3978.75,1952 R11.1
NetR12_1: R12.1 U2.39 | length 902.6
  Top Layer w10: U2.39 3464.53,1905.53 3494,1935 3867.42,1935 R12.1
NetR13_1: R13.1 U2.38 | length 907.7
  Top Layer w10: U2.38 3484.21,1888.21 3509,1913 3761.09,1913 R13.1
NetR14_2: R14.2 U2.12 | length 829.4
  Top Layer w10: U2.12 3503.9,1254.14 3598.03,1160 R14.2
NetR15_1: R15.1 U2.37 | length 916.9
  Top Layer w10: U2.37 3503.9,1877.9 3517,1891 3654.75,1891 R15.1
NetR16_2: R16.2 U2.13 | length 721.6
  Top Layer w10: U2.13 3523.58,1324.42 3574.67,1273.33 R16.2
NFAULT: J3.14 JP1.2 TP18.1 U1.16 | length 7048
  Top Layer w10: U1.16 1815.23,2776.77 1832,2760 v3(1870,2760) ; v2(4400,2555.61) 4863.61,2092 J3.14
  Bottom Layer w10: v3@1870,2758.86 v3(1870,2760) 2090,2540 JP1.2 2320,2550 2366,2596 2871,2596 2976,2491 3251,2491 3355,2595 3435,2595 3474.39,2555.61 v2(4400,2555.61) 4617.61,2555.61 4871,2809 4871,3959 4810,4020 4603.82,4020 4595.82,4012 4017,4012 3996,3991 3996,3636.71 3896,3536.71 3896,3282 TP18.1
NSLEEP: J3.11 R10.2 TP1.1 U1.1 | length 8017.4
  Top Layer w12: v1(1200,2025) v1(1515,2025) ; U1.1 v1(1540,3015) ; R10.2 4812,1900 J3.11 4979,1792 5002,1815 5002,3154 4923,3233 4567,3233 TP1.1
  Bottom Layer w12: v1(1200,2025) 1200,2535 1125,2610 1125,2955 1185,3015 v1(1540,3015) ; v1(1515,2025) 2415,2025 2550,2160 3123,2160 3125,2162 3343,2162 3362,2181 4531,2181 J3.11
OSCI: U3.27
OSCO: U3.28
P6M5: R8.2 U2.4 | length 508.5
  Top Layer w12: R8.2 3188,1380 3233,1335 3327.42,1335 3346.42,1354 U2.4
PVDD: JP3.1 U2.1 U2.64 | length 1398.8
  Top Layer w10: v1(3070,1460) 3212.53,1460 U2.64@3214.53,1462 ; U2.64@3214.17,1462 U2.64@3214.53,1462 ; U2.64 U2.64@3214.53,1462 ; U2.1 3245.47,1389.53 3214.53,1420.47 U2.64@3214.53,1462
  Bottom Layer w10: JP3.1 2960,1130 3070,1240 v1(3070,1460)
RI: U3.6
RST: J7.11 R9.1 S5.2 U2.58 | length 1578.9
  Top Layer w12: R9.1 2075,1615 2275,1415 S5.2 2449.85,1281.85 2473,1305 J7.11 2662,1352 2736,1352 2959,1575 3124,1575 3130,1581 U2.58@3214,1581
RTS: U3.3
RX: U2.32 U3.5 | length 2874.1
  Top Layer w10: U3.5 1509.55,1103.25 1509.55,1141.35 1539.2,1171 1685,1171 1940,1426 1940,1829 2030,1919 2736,1919 2822,1833 v2(2822,1827) ; v3(3497,1679) 3540.02,1679 3616.4,1755.37 3653.21,1755.37 U2.32
  Bottom Layer w12: v2(2822,1827) 2970,1679 v3@3489,1679
STEP/BENBL: J3.9 R12.2 TP11.1 U1.11 | length 9413.8
  Top Layer w12: v1(1395,849) 2506,849 2545,810 3650,810 3796,956 4696,956 4719,979 v1(4815.94,979) ; v1(1467,2590) 1467,2624 1481,2638 1481,2706 1500.59,2725.59 U1.11 ; R12.2 4868.67,1643.33 J3.9 5024,1592 5046,1614 5046,3467 4998,3515 4567,3515 TP11.1
  Bottom Layer w12: v1(1395,849) 1395,944 1393,946 1393,2236 1420,2263 1420,2426 1467,2473 v1(1467,2590) ; v1(4815.94,979) 4883.42,1046.47 4938.86,1046.47 4985.53,1093.14 4985.53,1526.47 J3.9
TX: U2.33 U3.1 | length 2977.4
  Top Layer w10: v3(3448,1709) 3532,1709 3582.64,1759.64 U2.33
  Top Layer w12: U3.1 1404.09,1139.67 1453.42,1189 1641.92,1189 1907,1454.08 1907,1848 2014,1955 v2(2775,1955)
  Bottom Layer w20: v2(2775,1955) 3019,1711 v3@3446,1711
USBDM: J6.2 U3.16 | length 1038.1
  Top Layer w12: J6.2 1052,1242 1632.69,1242 1711.18,1320.49 U3.16
USBDP: J6.3 U3.15 | length 1138.3
  Top Layer w12: J6.3 801.79,979.47 853.86,979.47 1088.39,1214 1635.81,1214 1736.77,1314.96
VCP: C5.2 TP17.1 U1.17 | length 3818
  Top Layer w12: U1.17 1755.93,2801 1852,2801 1860,2793 1930,2793 2028,2695 2097,2695 2134,2732 C5.2 2349,2776 v2(2350,2775) ; v2(3584,4275) 3888,4579 TP17.1
  Bottom Layer w12: v2(2350,2775) 2350,2776 3024,2776 3588.54,3340.54 3672.63,3340.54 3682,3349.91 3682,3707 3584,3805 v2(3584,4275)
VDD: C7.2 C8.1 C9.2 C14.1 J3.1 JP2.2 JP3.2 R5.1 R9.2 R17.2 REG1.5 TP23.1 U3.4 | length 7847.1
  Top Layer w12: v2(1480.87,922) U3.4 ; REG1.5 1648.51,704.51 1664,720 C14.1
  Top Layer w20: REG1.5 1605,707.51 v1(1605,745) ; C14.1 1917,720 1966,769 2071,769 R17.2 C9.2 v1@2355,765 ; v1(2005,2210) R5.1 ; R9.2 C7.2 2385,1705 JP2.2 ; v1(2356,766) v1@2355,765 ; JP3.2 2860,480 2915,535 2915,645 C8.1 2860,765 ; J3.1 4665,792 4638,765 2860,765 ; v1@2355,765 2356,765 2860,765
  Bottom Layer w20: v2@1475,927.87 v2(1480.87,922) ; TP23.1 1605,505 v1(1605,745) ; v1@1595,755 1480.87,869.13 v2(1480.87,922) ; v1(2005,2210) 1525,2210 1475,2160 1475,1021 1480.87,1015.13 v2(1480.87,922) ; v1(2356,766) 2356,1626 JP2.2 JP2.2@2435,1712.34
VINT: C4.2 TP16.1 U1.20 | length 3991
  Top Layer w12: U1.20 1824.25,2879.13 1833.11,2888 v3(1873,2888) ; v3@1876,2885 C4.2
  Bottom Layer w12: v3(1873,2888) 1919,2888 2182,2625 2868,2625 2985,2508 3195,2508 3313,2626 3313,2999.44 3632.1,3318.54 3681.74,3318.54 3704,3340.8 3704,3716.11 3682,3738.11 3682,4560 3682,4561 TP16.1@3700,4579
VM: C1.1 C2.2 C3.2 C5.1 J1.1 JP4.2 TP22.1 U1.18 U1.19 | length 4263.5
  Top Layer w50: JP4.2 440,2056 263,2233 263,3716 347,3800 J1.1 ; TP22.1 J1.1 ; v1(1700,3725) 1697,3722 1530,3722 1452,3800 C1.1 J1.1
  Bottom Layer w50: v1@1792,3675 1792,3575 2050,3317 2050,3125 2050,3093
  other v1: 2025,3075 2075,3075 2025,3125 2075,3125 1700,3675 1750,3675 1800,3675 1750,3725 1800,3725
VREFO: R6.1 R7.1 TP13.1 U1.24 | length 4423.8
  Top Layer w10: U1.24 1789.5,2981.5 1842,3034 v3(1873,3034) ; R6.1 3743,2793.04 3743,3294.25 3678.14,3359.11 3655.89,3359.11 3645,3370 R7.1 3856,3588.54 3856,4191 4244,4579 TP13.1
  Bottom Layer w10: v3(1873,3034) 2240,3034 ; 2242,3036 2240,3034 ; R7.1@3640.04,3382.5 3208.64,3382.5 3118.64,3292.5 3007.5,3292.5 2749,3034 2240,3034 ; R7.1 R7.1
pads on no net: J7.6 J7.8 J7.10 J7.12 J7.13 J7.14 R1.1 R2.1 U2.2 U2.3 U2.10 U2.11 U2.14 U2.15 U2.16 U2.17 U2.18 U2.19 U2.20 U2.21 U2.22 U2.23 U2.24 U2.25 U2.26 U2.27 U2.28 U2.29 U2.30 U2.31 U2.34 U2.35 U2.36 U2.44 U2.45 U2.46 U2.47 U2.48 U2.50 U2.51 U2.52 U2.53 U2.59 U2.60 U2.61 U3.8 U3.19 U3.24

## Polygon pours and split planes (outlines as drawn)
GND on Top Layer "Top GND Plane" (solid, pour order 1007): 200,200 5200,200 5200,4700 200,4700 200,200
BOUT2 on Top Layer "TOP_BOUT2" (solid, pour order 1006): 1307,2737 1441,2737 1447,2743 1491,2787 1521,2787 1576,2787 1576,2766 1501,2766 1493,2758 1422,2687 1398,2687 1307,2687 1307,2737
BISEN on Top Layer "TOP_BISEN" (solid, pour order 1005): 1273,2777 1429,2777 1437,2785 1465,2813 1516,2813 1576,2813 1576,2791 1484,2791 1437,2744 1273,2744 1273,2777
BOUT1 on Top Layer "TOP_BOUT1" (solid, pour order 1004): 1307,2789 1430,2789 1445,2804 1458,2817 1515,2817 1576,2817 1576,2839 1308,2839 1307,2838 1307,2789
AOUT2 on Top Layer "TOP_AOUT2" (solid, pour order 1003): 1304,2895 1407,2895 1441,2861 1577,2861 1577,2842 1415,2842 1414,2843 1411,2846 1307,2846 1307,2878 1304,2881 1304,2895
AISEN on Top Layer "TOP_AISEN" (solid, pour order 1002): 1272,2937 1431,2937 1444,2924 1478,2890 1509,2890 1576,2890 1576,2868 1447,2868 1417,2898 1412,2903 1389,2903 1272,2903 1272,2937
AOUT1 on Top Layer "TOP_AOUT1" (solid, pour order 1001): 1339,2993 1422,2993 1500,2915 1575,2915 1575,2895 1480,2895 1433,2942 1339,2942
VM on Top Layer "TOP_VM" (solid, pour order 1000): 1725,2860 1790,2860 1795,2865 1973,2865 1994,2886 1994,3151 2098,3151 2099,2736 2058,2736 1987,2810 1800,2810 1795,2815 1725,2815
GND on Bottom Layer "Bottom GND Plane" (solid, pour order 1008): 200,200 5200,200 5200,4700 200,4700 200,200

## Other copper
Top Layer:
  rectangle net VM: 1675,3655 1825,3750
  text "Top Layer" at 5313,4593 h60
Bottom Layer:
  rectangle net VM: 1675,3655 1825,3750
  rectangle net VM: 1990,3050 2100,3175
  text "Bottom Layer" at 5318,4421 h60

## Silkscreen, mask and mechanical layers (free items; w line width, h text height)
Top Overlay:
  drawing of 102 lines, arcs and shapes, not listed
  text "1.MSP430" at 1195,4115 h48
  text "1.MSP430" at 2560,4115 h48
  text "2.External" at 1195,3997.5 h48
  text "2.External" at 2560,3997.5 h48
  text "3.POT" at 1195,3880 h48
  text "3.POT" at 2560,3880 h48
  text "1.AVREF" at 2565,3440 h48
  text "2.MSP430" at 2565,3325 h48
  text "3.External" at 2565,3210 h48
  text "4.POT" at 2565,3095 h48
  text "AOUT1" at 645,3075.01 h50
  text "AOUT2" at 636.67,2875.01 h50
  text "1.MSP430" at 2545,2740 h48
  text "BOUT1" at 645,2675.01 h50
  text "2.External" at 2545,2622.5 h48
  text "!" at 1663,2528 h60
  text "3.POT" at 2545,2505 h48
  text "BOUT2" at 636.67,2475.01 h50
  text "WARNING" at 1475,2325 h60
  text "JP1: nFAULT" at 2357,2292 h40
  text "U1 may get hot" at 1300,2250 h48
  text "nFAULT" at 4560,2064.01 h48
  text "BDECAY" at 4560,1964.01 h48
  text "ADECAY" at 4560,1864.01 h48
  text "nSLEEP" at 4560,1764.01 h48
  text "VM Supply" at 259,1672 h60
  text "DIR/BPHASE" at 4376.06,1664.01 h48
  text "STEP/BENBL" at 4368.06,1564.01 h48
  text "JTAG TRGT" at 2277,1493 h30
  text "M0/APHASE" at 4416.05,1464.01 h48
  text "nENBL/AENBL" at 4320.08,1364.01 h48
  text "CONFIG" at 4568,1264.01 h48
  text "M1" at 4767.93,1164.01 h48
  text "AVREF" at 4607.98,1064.01 h48
  text "BVREF" at 4607.98,964.01 h48
  text "MCU_RST" at 2087,948 h60
  text "GND" at 4703.95,864.01 h48
  text "VDD" at 4703.95,764.01 h48
  text "External Input" at 4360,565 h60
  text "DRV8834EVM RevA" at 3640,270 h60
  text "2/17/2012" at 850,230 h40
Mechanical 1:
  the board outline again, w8
Drill Drawing:
  text ".Legend" at 5840,1845 h40

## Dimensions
200,200 to 5200,200 on Mechanical 1
123,188 to 53,4688 on Mechanical 1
